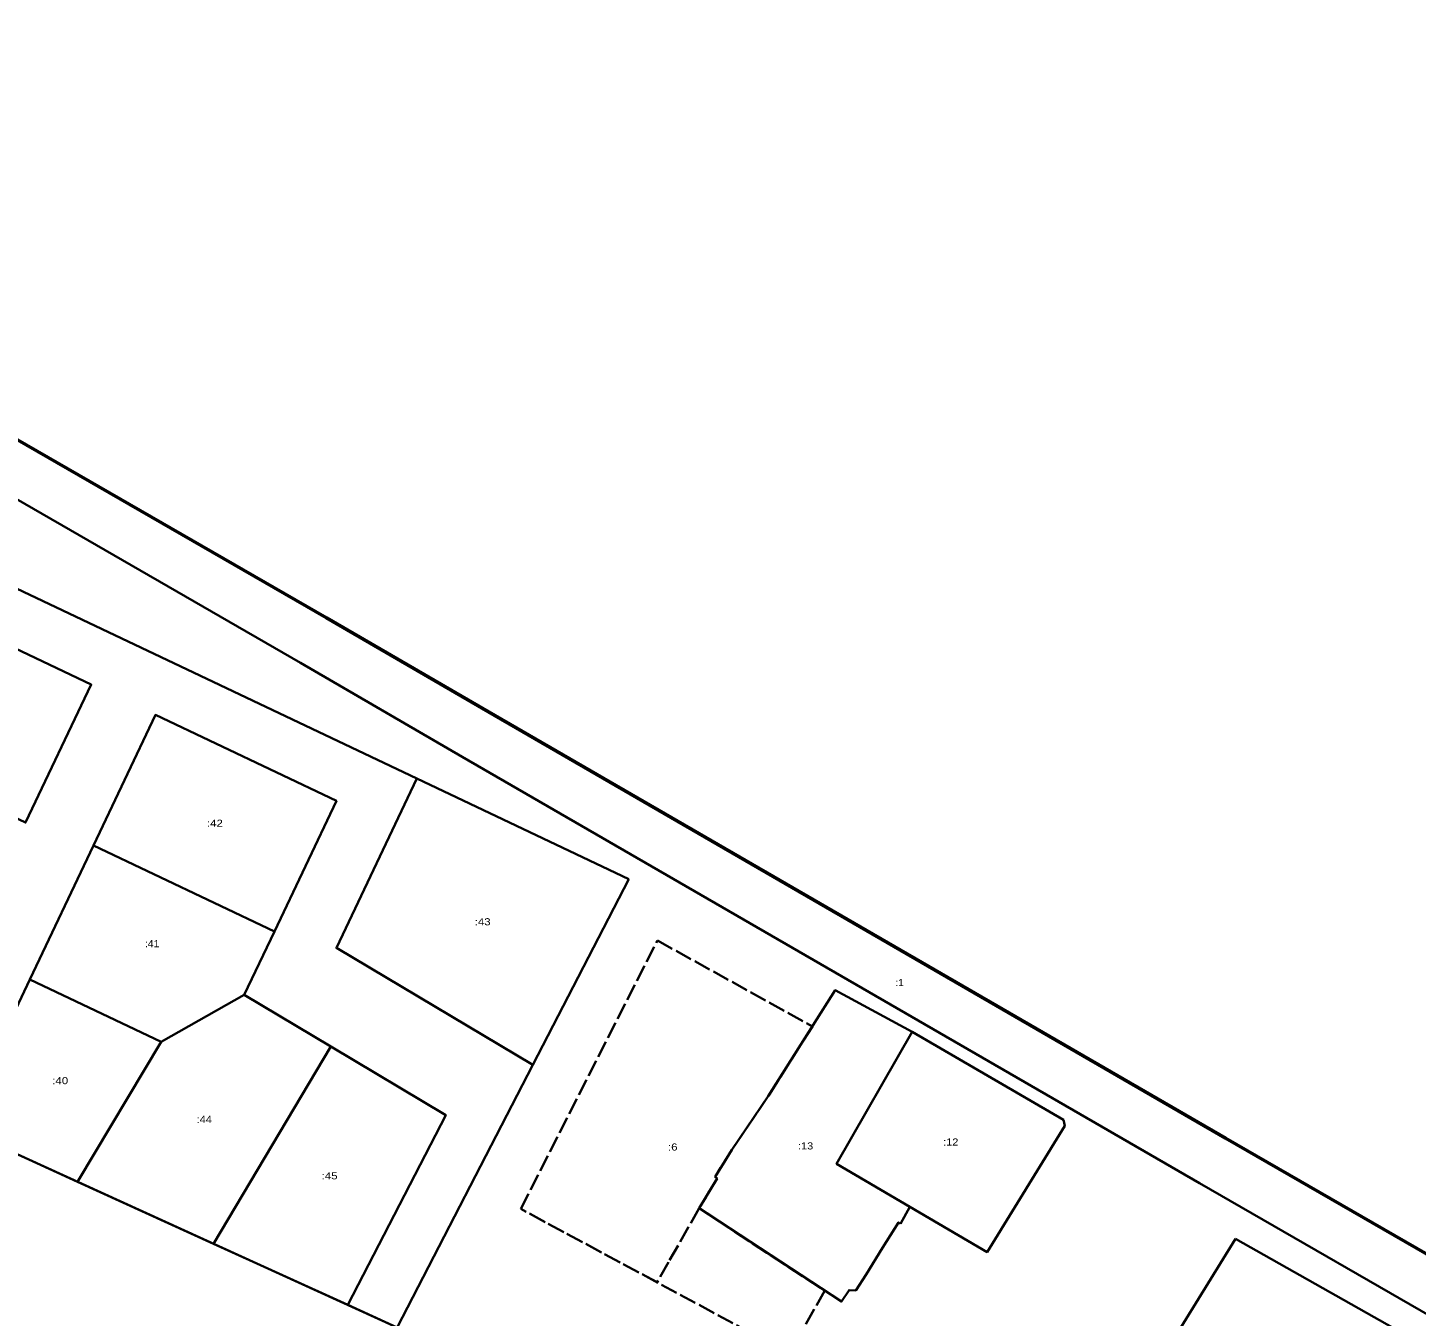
# Model space of a CAD drawing. Extents: x 1178597 to 1179642, y 361068 to 362800.
# Drawn here: x 1179189.1 to 1179482.1, y 362404.2 to 362676.1 of the extents above; entities that cross this region are included whole.
import ezdxf
from ezdxf.enums import TextEntityAlignment as Align

# ---------------------------------------------------------------- set-up
doc = ezdxf.new("R2010")
doc.units = 0
doc.header["$LTSCALE"] = 0.6
doc.linetypes.add('LONG_DASHED', pattern=[7.5, 6, -1.5])
for name, color, linetype, lineweight in [('2', 7, 'Continuous', 35), ('4', 7, 'Continuous', 53), ('57', 7, 'LONG_DASHED', 35)]:
    doc.layers.add(name, color=color, linetype=linetype, lineweight=lineweight)

msp = doc.modelspace()

# ---------------------------------------------------------------- linework, layer by layer
at = {"layer": '2'}
for points in [[(1178937.29, 362676.13), (1179271.17, 362517.67), (1179254.21, 362481.92), (1179295.66, 362457.21), (1179267.04, 362401.8), (1179256.58, 362406.56), (1179277.28, 362446.63), (1179253.05, 362461.08), (1179234.75, 362471.99), (1179241.11, 362485.39), (1179254.2, 362512.95), (1179216, 362531.08), (1179202.92, 362503.52), (1179189.51, 362475.25), (1179174.63, 362443.93)], [(1179126.54, 362623.96), (1179252.11, 362551.57), (1179286.27, 362531.76), (1179441.83, 362441.77), (1179499.74, 362408.44), (1179525.44, 362393.35), (1179549.05, 362380.04), (1179620.68, 362339.09), (1179641.66, 362326.26), (1179640.88, 362325.28), (1179636.71, 362327.82), (1179630.82, 362320), (1179615.08, 362329.62), (1179543.62, 362370.48), (1179519.96, 362383.81), (1179494.22, 362398.93), (1179436.33, 362432.25), (1179280.76, 362522.24), (1179246.62, 362542.08), (1179121.07, 362614.45)], [(1179188.61, 362508.37), (1179202.44, 362537.51), (1179174.44, 362550.8)]]:
    msp.add_lwpolyline(points, dxfattribs=at)
for points in [[(1178891.19, 362573.17), (1179267.04, 362401.8), (1179192.55, 362243.52), (1179468.78, 362106.45), (1179321.34, 361904.3), (1179281.73, 361911.69), (1179245.3, 361911.43), (1179204.36, 361904.31), (1179180.02, 361887.37), (1179148.05, 361900.8), (1179128.65, 361905.22), (1179097.75, 361928.91), (1179058.81, 361961.65), (1179007.74, 362014.5), (1178950.38, 362075.56), (1178913.62, 362120.85), (1178888.23, 362168.49), (1178869.92, 362263.16), (1178889.76, 362516.06)], [(1179174.44, 362550.8), (1179202.44, 362537.51), (1179188.61, 362508.37), (1179160.61, 362521.66)], [(1179216, 362531.08), (1179254.2, 362512.95), (1179241.11, 362485.39), (1179202.92, 362503.52)], [(1179315.92, 362496.43), (1179271.17, 362517.67), (1179254.21, 362481.92), (1179295.66, 362457.21)], [(1179202.92, 362503.52), (1179241.11, 362485.39), (1179234.75, 362471.99), (1179217.19, 362462.12), (1179189.51, 362475.25)], [(1179189.51, 362475.25), (1179217.19, 362462.12), (1179199.57, 362432.57), (1179174.63, 362443.93)], [(1179234.75, 362471.99), (1179253.05, 362461.08), (1179228.24, 362419.49), (1179199.57, 362432.57), (1179217.19, 362462.12)], [(1179373.27, 362423.71), (1179372.83, 362423.97), (1179369.48, 362418.64), (1179366.03, 362412.96), (1179363.8, 362409.63), (1179362.39, 362409.69), (1179360.77, 362407.28), (1179330.74, 362426.96), (1179334.52, 362433.25), (1179334.13, 362433.58), (1179337.63, 362439.31), (1179345.35, 362450.66), (1179359.47, 362472.98), (1179375.7, 362464.19), (1179359.77, 362436.35), (1179375.24, 362427.26)], [(1179375.7, 362464.19), (1179407.63, 362445.62), (1179407.92, 362444.38), (1179391.53, 362417.71), (1179375.24, 362427.26), (1179359.77, 362436.35)], [(1179253.05, 362461.08), (1179277.28, 362446.63), (1179256.58, 362406.56), (1179228.24, 362419.49)], [(1179443.93, 362420.54), (1179477.56, 362401.53), (1179464.51, 362372.54), (1179457.54, 362363.24), (1179441.32, 362373.15), (1179438.43, 362369.32), (1179419.28, 362379.91), (1179422.59, 362385.8)]]:
    msp.add_lwpolyline(points, close=True, dxfattribs=at)
at = {"layer": '2', "linetype": 'LONG_DASHED'}
msp.add_lwpolyline([(1179321.94, 362483.47), (1179354.64, 362465.35), (1179345.35, 362450.66), (1179337.63, 362439.31), (1179334.13, 362433.58), (1179334.52, 362433.25), (1179330.74, 362426.96), (1179324.3, 362415.62), (1179321.868, 362411.337), (1179293.1, 362426.82)], close=True, dxfattribs=at)
at = {"layer": '4'}
msp.add_lwpolyline([(1179518.35, 362177.86), (1179556.38, 362223.96), (1179634.96, 362317.55), (1179641.66, 362326.26), (1179620.68, 362339.09), (1179549.05, 362380.04), (1179525.44, 362393.35), (1179499.74, 362408.44), (1179441.83, 362441.77), (1179286.27, 362531.76), (1179252.11, 362551.57), (1179099.35, 362639.55)], dxfattribs=at)
at = {"layer": '57'}
msp.add_lwpolyline([(1179321.94, 362483.47), (1179354.64, 362465.35), (1179345.35, 362450.66), (1179337.63, 362439.31), (1179334.13, 362433.58), (1179334.52, 362433.25), (1179330.74, 362426.96), (1179357.26, 362409.58), (1179349.75, 362396.33), (1179293.1, 362426.82)], close=True, dxfattribs=at)

# ---------------------------------------------------------------- texts
at = {"layer": '2'}
for s, width, p in [(':42', 1.2, (1179228.559, 362507.485)), (':43', 1.2, (1179285.065, 362486.69)), (':41', 1.1, (1179215.31, 362482.07)), (':1', 1.05, (1179373.04, 362473.853)), (':40', 1.2, (1179195.91, 362453.16)), (':44', 1.15, (1179226.31, 362444.99)), (':12', 1.15, (1179383.845, 362440.2)), (':6', 1.2, (1179325.181, 362439.15)), (':45', 1.2, (1179252.759, 362433.07))]:
    msp.add_text(s, height=1.5, dxfattribs=dict(at, width=width)).set_placement(p, align=Align.CENTER)
at = {"layer": '57', "width": 1.15}
msp.add_text(':13', height=1.5, dxfattribs=at).set_placement((1179353.22, 362439.38), align=Align.CENTER)

doc.saveas('drawing.dxf')
